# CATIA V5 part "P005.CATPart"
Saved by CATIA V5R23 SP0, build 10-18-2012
Part number: P005
Definition: Axe du levier
Bounding box of the stored display mesh (mm): x -48 to 48, y -12.5 to 12.5, z -12.5 to 12.5
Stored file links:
  C:\wamp\www\COURS\CONCEPTION GMP1\TITRE 02-SEMESTRE 2\03-TP7-PRESSE MECANIQUE\eleve\P005.CATPart
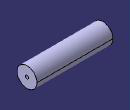
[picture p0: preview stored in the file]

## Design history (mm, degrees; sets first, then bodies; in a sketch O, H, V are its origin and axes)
Body1 (main body)
  Sketch1 on yz-plane, origin (0, 0, 0), H (0, 1, 0), V (0, 0, 1)
    circle A1 centre (0, 0) radius 12.5
    radius A1 = 12.5
  Pad1: profile Sketch1, direction (1, 0, 0), length 48, mirrored extent
  Sketch2 on face of Pad1, origin (48, 0, 0), H (0, 1, 0), V (0, 0, 1)
    point P1 (0, 0)
  Hole1: placed by Sketch2, at (48, 0, 0) direction (-1, 0, 0), diameter 4.134, depth 10, V-bottom angle 120, threaded "M5", thread diameter 5, thread depth 8, pitch 0.8
  Sketch3 on face of Pad1, origin (-48, 0, 0), H (0, 1, 0), V (0, 0, -1)
    point P1 (0, 0)
  Hole2: placed by Sketch3, at (-48, 0, 0) direction (1, 0, 0), diameter 4.134, depth 10, V-bottom angle 120, threaded "M5", thread diameter 5, thread depth 8, pitch 0.8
